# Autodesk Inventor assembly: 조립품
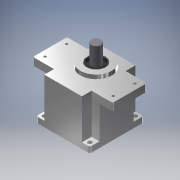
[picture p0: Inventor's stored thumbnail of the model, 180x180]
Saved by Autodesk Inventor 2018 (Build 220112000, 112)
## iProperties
Created: 2020-07
Part Number: 조립품
Material: 일반
Document SubType Name: Assembly
Designer: Admin
Author: Admin
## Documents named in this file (10)
- C:\Users\Admin\Desktop\700707V1012\조립품.iam
- C:\Users\Admin\Desktop\700707V1012\본체.ipt
- C:\Users\Admin\Desktop\700707V1012\커버.ipt
- C:\Users\Admin\Desktop\700707V1012\볼트 M4.ipt
- C:\Users\Admin\Desktop\700707V1012\메인 축.ipt
- C:\Users\Admin\Desktop\700707V1012\서브 축.ipt
- C:\Users\Admin\Desktop\700707V1012\베어링 608.ipt
- C:\Users\Admin\Desktop\700707V1012\베어링 6003.ipt
- C:\Users\Admin\Desktop\700707V1012\오일 실 17 32 8.ipt
- C:\Users\Admin\Desktop\700707V1012\오일 실 8 22 7.ipt
